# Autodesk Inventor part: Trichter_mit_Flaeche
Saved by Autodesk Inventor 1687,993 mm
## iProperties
Created: 2010-10
Part Number: Trichter_mit_Flaeche
Material: 1.4301
Document SubType Name: Blech
Designer: Tim Müller
Density: 7.9 g/cm^3
Flat Pattern Width: 168.799 cm
Flat Pattern Length: 135.573 cm
Flat Pattern Area: 22884.6 cm^2
Sheet Metal Rule: 14301_1,5mm
Mass: 33435.2 g
Surface Area: 56522.3 cm^2
Volume: 4232.3 cm^3
Sheet Metal Width: 1355,727 mm
Sheet Metal Length: 2288457,611 mm^2
Author: Tim Müller
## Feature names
1. Biegung1
